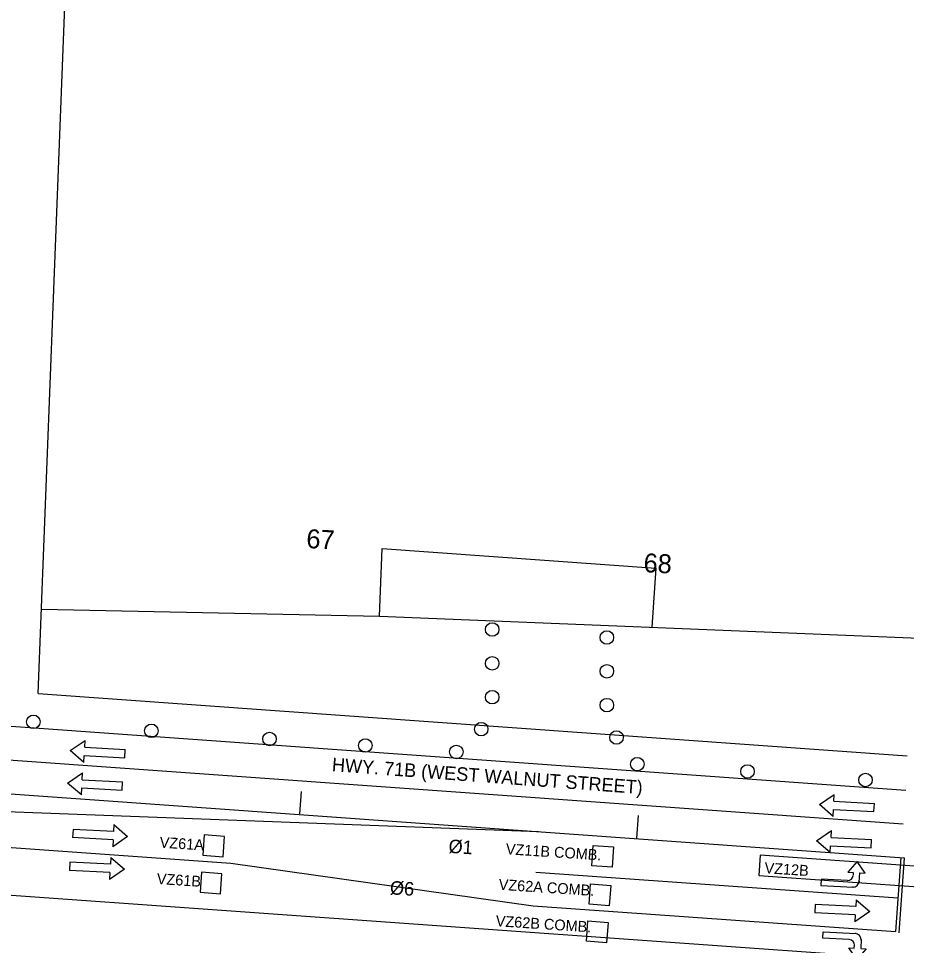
# Model space of a CAD drawing. Extents: x 0 to 1361828, y 0 to 1470398.
# Drawn here: x 685888.8 to 686151.5, y 734825.2 to 735099.3 of the extents above; entities that cross this region are included whole.
import ezdxf

# ---------------------------------------------------------------- set-up
doc = ezdxf.new("R2010")
doc.units = 0
for name, color, linetype in [('$', 7, 'Continuous'), ('BASE', 7, 'Continuous'), ('MOT Stage 1', 7, 'Continuous'), ('MOT Stage 1 Lanes', 7, 'Continuous'), ('R_Horz Alg Station', 7, 'Continuous'), ('RW-EX', 7, 'Continuous'), ('RW-PR', 7, 'Continuous'), ('SIGNAL-PR$', 7, 'Continuous'), ('TITEXT', 7, 'Continuous'), ('Video-Zones-pr', 7, 'Continuous')]:
    doc.layers.add(name, color=color, linetype=linetype)

# ---------------------------------------------------------------- blocks, each defined once
blk = doc.blocks.new('BAREL_1780')
at = {"layer": 'MOT Stage 1'}
blk.add_circle((0, 0.01), 2.88, dxfattribs=at)
blk = doc.blocks.new('BAREL_1781')
at = {"layer": 'MOT Stage 1'}
blk.add_circle((0, 0.01), 2.88, dxfattribs=at)
blk = doc.blocks.new('BAREL_1782')
at = {"layer": 'MOT Stage 1'}
blk.add_circle((0, 0.01), 2.88, dxfattribs=at)
blk = doc.blocks.new('BAREL_1783')
at = {"layer": 'MOT Stage 1'}
blk.add_circle((0, 0.01), 2.88, dxfattribs=at)
blk = doc.blocks.new('BAREL_1784')
at = {"layer": 'MOT Stage 1'}
blk.add_circle((0, 0.01), 2.88, dxfattribs=at)
blk = doc.blocks.new('BAREL_1785')
at = {"layer": 'MOT Stage 1'}
blk.add_circle((0, 0.01), 2.88, dxfattribs=at)
blk = doc.blocks.new('SARROW_207')
at = {"layer": 'MOT Stage 1'}
for p, q in [((0, 0), (-6, 0)), ((0, -29.42), (0, 0)), ((-6, -29.42), (-6, 0)), ((-6, -29.42), (-11, -29.42)), ((-3, -39.81), (-11, -29.42)), ((5, -29.42), (-3, -39.81)), ((5, -29.42), (0, -29.42))]:
    blk.add_line(p, q, dxfattribs=at)
blk = doc.blocks.new('SARROW_208')
at = {"layer": 'MOT Stage 1'}
for p, q in [((-6, -29.42), (-6, 0)), ((0, 0), (-6, 0)), ((0, -29.42), (0, 0)), ((-6, -29.42), (-11, -29.42)), ((-3, -39.81), (-11, -29.42)), ((5, -29.42), (-3, -39.81)), ((5, -29.42), (0, -29.42))]:
    blk.add_line(p, q, dxfattribs=at)
blk = doc.blocks.new('SARROW_209')
at = {"layer": 'MOT Stage 1'}
for p, q in [((-6, -29.42), (-6, 0)), ((0, 0), (-6, 0)), ((0, -29.42), (0, 0)), ((-6, -29.42), (-11, -29.42)), ((-3, -39.81), (-11, -29.42)), ((5, -29.42), (-3, -39.81)), ((5, -29.42), (0, -29.42))]:
    blk.add_line(p, q, dxfattribs=at)
blk = doc.blocks.new('SARROW_213')
at = {"layer": 'MOT Stage 1'}
for p, q in [((0, 0), (-6, 0)), ((0, -29.42), (0, 0)), ((-6, -29.42), (-6, 0)), ((-6, -29.42), (-11, -29.42)), ((-3, -39.81), (-11, -29.42)), ((5, -29.42), (-3, -39.81)), ((5, -29.42), (0, -29.42))]:
    blk.add_line(p, q, dxfattribs=at)
blk = doc.blocks.new('SARROW_214')
at = {"layer": 'MOT Stage 1'}
for p, q in [((-6, -29.42), (-6, 0)), ((0, 0), (-6, 0)), ((0, -29.42), (0, 0)), ((-6, -29.42), (-11, -29.42)), ((-3, -39.81), (-11, -29.42)), ((5, -29.42), (-3, -39.81)), ((5, -29.42), (0, -29.42))]:
    blk.add_line(p, q, dxfattribs=at)
blk = doc.blocks.new('SARROW_215')
at = {"layer": 'MOT Stage 1'}
for p, q in [((0, 0), (-6, 0)), ((0, -29.42), (0, 0)), ((-6, -29.42), (-6, 0)), ((-6, -29.42), (-11, -29.42)), ((-3, -39.81), (-11, -29.42)), ((5, -29.42), (-3, -39.81)), ((5, -29.42), (0, -29.42))]:
    blk.add_line(p, q, dxfattribs=at)
blk = doc.blocks.new('SARROW_216')
at = {"layer": 'MOT Stage 1'}
for p, q in [((0, 0), (-6, 0)), ((0, -29.42), (0, 0)), ((-6, -29.42), (-6, 0)), ((-6, -29.42), (-11, -29.42)), ((-3, -39.81), (-11, -29.42)), ((5, -29.42), (-3, -39.81)), ((5, -29.42), (0, -29.42))]:
    blk.add_line(p, q, dxfattribs=at)
blk = doc.blocks.new('BAREL_1819')
at = {"layer": 'MOT Stage 1'}
blk.add_circle((0, 0.01), 2.88, dxfattribs=at)
blk = doc.blocks.new('BAREL_1820')
at = {"layer": 'MOT Stage 1'}
blk.add_circle((0, 0.01), 2.88, dxfattribs=at)
blk = doc.blocks.new('BAREL_1821')
at = {"layer": 'MOT Stage 1'}
blk.add_circle((0, 0.01), 2.88, dxfattribs=at)
blk = doc.blocks.new('BAREL_1822')
at = {"layer": 'MOT Stage 1'}
blk.add_circle((0, 0.01), 2.88, dxfattribs=at)
blk = doc.blocks.new('BAREL_1868')
at = {"layer": 'MOT Stage 1'}
blk.add_circle((0, 0.01), 2.88, dxfattribs=at)
blk = doc.blocks.new('BAREL_1869')
at = {"layer": 'MOT Stage 1'}
blk.add_circle((0, 0.01), 2.88, dxfattribs=at)
blk = doc.blocks.new('BAREL_1911')
at = {"layer": 'MOT Stage 1'}
blk.add_circle((0, 0.01), 2.88, dxfattribs=at)
blk = doc.blocks.new('BAREL_1912')
at = {"layer": 'MOT Stage 1'}
blk.add_circle((0, 0.01), 2.88, dxfattribs=at)
blk = doc.blocks.new('BAREL_1913')
at = {"layer": 'MOT Stage 1'}
blk.add_circle((0, 0.01), 2.88, dxfattribs=at)
blk = doc.blocks.new('BAREL_1914')
at = {"layer": 'MOT Stage 1'}
blk.add_circle((0, 0.01), 2.88, dxfattribs=at)

msp = doc.modelspace()

# ---------------------------------------------------------------- linework, layer by layer
at = {"layer": 'MOT Stage 1'}
for points in [[(686137.54, 734844.26), (686137.52, 734843.94), (686137.66, 734846.67), (686139.25, 734846.59), (686136.89, 734850.01), (686134.18, 734846.86), (686135.76, 734846.77), (686135.72, 734845.95)], [(686134.05, 734844.44), (686126.26, 734844.86), (686126.16, 734842.95)], [(686126.16, 734842.95), (686135.85, 734842.44), (686135.53, 734842.46)], [(686134.58, 734826.93), (686126.73, 734827.35), (686126.83, 734829.27)], [(686126.83, 734829.27), (686136.59, 734828.75), (686136.28, 734828.77)], [(686138.09, 734826.75), (686138.11, 734827.07), (686137.96, 734824.32), (686139.56, 734824.23), (686136.83, 734821.05), (686134.45, 734824.5), (686136.05, 734824.42), (686136.09, 734825.25)]]:
    msp.add_lwpolyline(points, dxfattribs=at)
for centre, radius, start, end in [((686134.13, 734846.03), 1.59, 266.9687, 356.9687), ((686135.63, 734844.36), 1.9, 266.9687, 356.9687), ((686136.17, 734826.85), 1.92, 356.9687, 86.9687), ((686134.49, 734825.34), 1.6, 356.9687, 86.9687)]:
    msp.add_arc(centre, radius, start, end, dxfattribs=at)
at = {"layer": 'MOT Stage 1 Lanes'}
for p, q in [((685868.12, 734865.51), (686042.67, 734858.89)), ((685867.4, 734855.54), (685951.66, 734849.51)), ((685951.66, 734849.51), (686041.1, 734836.95))]:
    msp.add_line(p, q, dxfattribs=at)
for points in [[(685869.96, 734891.29), (686151.25, 734871.18)], [(685869.25, 734881.32), (686150.53, 734861.21)], [(685868.53, 734871.34), (686150.82, 734851.16)], [(686149.82, 734851.23), (686148.25, 734829.29)], [(686150.82, 734851.16), (686149.23, 734828.94)], [(686041.81, 734846.92), (686148.96, 734839.26)], [(686041.1, 734836.95), (686148.25, 734829.29)]]:
    msp.add_lwpolyline(points, dxfattribs=at)
at = {"layer": 'R_Horz Alg Station'}
for points in [[(685972.4, 734870.76), (685971.92, 734864.11)], [(686072.14, 734863.63), (686071.67, 734856.98)]]:
    msp.add_lwpolyline(points, dxfattribs=at)
at = {"layer": 'RW-EX'}
for p, q in [((685894.65, 734899.71), (685906.88, 735216.51)), ((685894.65, 734899.71), (686151.72, 734881.33)), ((685615.93, 734859.48), (686148.06, 734821.44))]:
    msp.add_line(p, q, dxfattribs=at)
at = {"layer": 'RW-PR'}
for p, q in [((685995.63, 734922.56), (685996.43, 734942.56)), ((685996.43, 734942.56), (686077.37, 734936.77))]:
    msp.add_line(p, q, dxfattribs=at)
for points in [[(686077.37, 734936.77), (686076.12, 734919.3)], [(685895.62, 734924.7), (685995.63, 734922.56), (686160.19, 734915.9)]]:
    msp.add_lwpolyline(points, dxfattribs=at)
at = {"layer": 'Video-Zones-pr'}
for points in [[(685949.32, 734851.4), (685949.75, 734857.39), (685943.77, 734857.9), (685943.34, 734851.91), (685949.32, 734851.4)], [(685942.99, 734846.92), (685942.56, 734840.94), (685948.54, 734840.43), (685948.96, 734846.41), (685942.99, 734846.92)], [(686057.6, 734837.46), (686058.03, 734843.45), (686064.01, 734842.94), (686063.58, 734836.95), (686057.6, 734837.46)], [(686063.22, 734831.96), (686062.8, 734825.98), (686056.82, 734826.49), (686057.25, 734832.48), (686063.22, 734831.96)]]:
    msp.add_lwpolyline(points, dxfattribs=at)
for points in [[(686064.4, 734848.35), (686058.41, 734848.78), (686058.84, 734854.76), (686064.82, 734854.33)], [(686158.04, 734848.35), (686108.17, 734851.9), (686107.82, 734845.91), (686157.7, 734842.36)]]:
    msp.add_lwpolyline(points, close=True, dxfattribs=at)

# ---------------------------------------------------------------- block references
at = {"layer": 'MOT Stage 1'}
for name, p, xscale, yscale, rotation in [('BAREL_1780', (686028.96, 734918.64), 0.6945420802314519, 0.6945420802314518, 87.04179557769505), ('BAREL_1781', (686062.88, 734916.29), 0.6945420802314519, 0.6945420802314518, 87.04179557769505), ('BAREL_1782', (686028.96, 734908.64), 0.6945420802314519, 0.6945420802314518, 87.04179557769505), ('BAREL_1784', (686062.88, 734906.29), 0.6945420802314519, 0.6945420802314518, 87.04179557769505), ('BAREL_1783', (686028.96, 734898.64), 0.6945420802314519, 0.6945420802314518, 87.04179557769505), ('BAREL_1785', (686062.88, 734896.29), 0.6945420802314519, 0.6945420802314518, 87.04179557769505), ('BAREL_1911', (685893.25, 734891.35), 0.6945420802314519, 0.6945420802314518, 87.04179557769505), ('BAREL_1912', (685928.15, 734888.67), 0.6945420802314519, 0.6945420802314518, 87.04179557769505), ('BAREL_1819', (686025.71, 734889.18), 0.6945420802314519, 0.6945420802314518, 87.04179557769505), ('BAREL_1913', (685963.07, 734886.27), 0.6945420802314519, 0.6945420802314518, 87.04179557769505), ('BAREL_1820', (686065.72, 734886.71), 0.6945420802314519, 0.6945420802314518, 87.04179557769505), ('SARROW_213', (685920.27, 734880.74), 0.40758735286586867, 0.4075873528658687, -93.03128829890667), ('BAREL_1914', (685991.43, 734884.35), 0.6945420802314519, 0.6945420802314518, 87.04179557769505), ('BAREL_1868', (686018.32, 734882.44), 0.6945420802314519, 0.6945420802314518, 87.04179557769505), ('BAREL_1869', (686071.86, 734878.81), 0.6945420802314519, 0.6945420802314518, 87.04179557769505), ('SARROW_214', (685919.51, 734871.16), 0.40758735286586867, 0.4075873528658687, -93.03128829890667), ('BAREL_1821', (686104.46, 734876.67), 0.6945420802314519, 0.6945420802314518, 87.04179557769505), ('BAREL_1822', (686139.37, 734874.15), 0.6945420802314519, 0.6945420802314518, 87.04179557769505), ('SARROW_208', (686141.85, 734864.78), 0.40758735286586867, 0.4075873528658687, -93.03128829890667), ('SARROW_215', (685904.97, 734859.53), 0.4075873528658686, 0.40758735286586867, 86.96871170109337), ('SARROW_207', (686141.01, 734854.06), 0.40758735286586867, 0.4075873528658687, -93.03128829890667), ('SARROW_216', (685904.03, 734849.85), 0.4075873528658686, 0.40758735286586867, 86.96871170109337), ('SARROW_209', (686124.51, 734837.32), 0.4075873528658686, 0.40758735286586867, 86.96871170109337)]:
    msp.add_blockref(name, p, dxfattribs=dict(at, xscale=xscale, yscale=yscale, rotation=rotation))

# ---------------------------------------------------------------- texts
at = {"layer": '$'}
for s, p in [('67', (685973.87, 734942.76)), ('68', (686073.62, 734935.63))]:
    msp.add_text(s, height=5.6, rotation=357.0415, dxfattribs=at).set_placement(p)
at = {"layer": 'BASE'}
msp.add_text('HWY. 71B (WEST WALNUT STREET)', height=4, rotation=355.7594, dxfattribs=at).set_placement((685981.44, 734876.76))
at = {"layer": 'SIGNAL-PR$'}
for s, p in [('VZ61A', (685930.51, 734854.15)), ('VZ11B COMB.', (686032.91, 734852.19)), ('VZ12B', (686109.42, 734846.58)), ('VZ61B', (685929.66, 734843.39)), ('VZ62A COMB.', (686030.79, 734841.69)), ('VZ62B COMB.', (686029.92, 734830.91))]:
    msp.add_text(s, height=3.2, rotation=356.2723, dxfattribs=at).set_placement(p)
at = {"layer": 'TITEXT'}
for s, p in [('%%C1', (686015.94, 734852.61)), ('%%C6', (685998.61, 734840.34))]:
    msp.add_text(s, height=4, rotation=356.2723, dxfattribs=at).set_placement(p)

doc.saveas('drawing.dxf')
